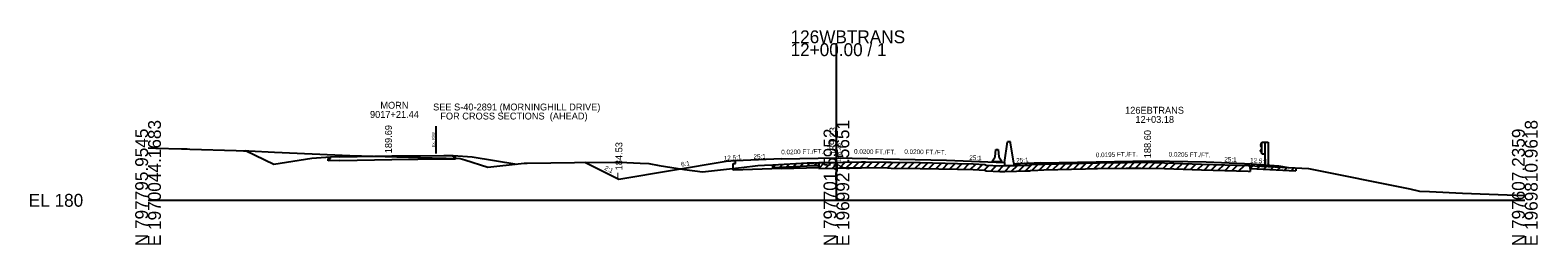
# Model space of a CAD drawing. Extents: x -6494 to 1970605, y -10 to 798140.
# Drawn here: x -25.7 to 302.8, y 4490.3 to 4537 of the extents above; entities that cross this region are included whole.
import ezdxf

# ---------------------------------------------------------------- set-up
doc = ezdxf.new("R2010")
doc.units = 0
for name, color, linetype in [('Default', 7, 'Continuous'), ('RD_GPK_XS_Cell', 7, 'Continuous'), ('RD_XS_Base', 7, 'Continuous'), ('RD_XS_EarthShd', 7, 'Continuous'), ('RD_XS_ExGround', 7, 'Continuous'), ('RD_XS_ExPaveRet', 7, 'Continuous'), ('RD_XS_ExRW', 7, 'Continuous'), ('RD_XS_GR', 7, 'Continuous'), ('RD_XS_MedBWall', 7, 'Continuous'), ('RD_XS_Misc_Line', 7, 'Continuous'), ('RD_XS_Pave', 7, 'Continuous'), ('RD_XS_PaveOvlay', 7, 'Continuous'), ('RD_XS_PaveShd', 7, 'Continuous'), ('RD_XS_TieSlope', 7, 'Continuous'), ('RD_XS_TX_Elev_EX', 7, 'Continuous'), ('RD_XS_TX_Elev_PR', 7, 'Continuous'), ('RD_XS_TX_Misc', 7, 'Continuous'), ('RD_XS_TX_MkPT', 7, 'Continuous'), ('RD_XS_TX_Notes', 7, 'Continuous'), ('RD_XS_TX_Profile', 7, 'Continuous'), ('RD_XS_TX_ShdSlope', 7, 'Continuous'), ('RD_XS_TX_Slope', 7, 'Continuous'), ('RD_XS_TX_Station', 7, 'Continuous')]:
    doc.layers.add(name, color=color, linetype=linetype)

msp = doc.modelspace()

# ---------------------------------------------------------------- linework, layer by layer
at = {"layer": 'Default'}
for p, q in [((184.58, 4509.45), (184.75, 4511.04)), ((184.75, 4511.04), (185.25, 4511.04)), ((185.25, 4511.04), (185.42, 4509.45)), ((184, 4508.62), (184.58, 4509.45)), ((184, 4508.37), (184, 4508.62)), ((186, 4508.37), (184, 4508.37)), ((185.42, 4509.45), (186, 4508.62)), ((186, 4508.62), (186, 4508.37))]:
    msp.add_line(p, q, dxfattribs=at)
at = {"layer": 'RD_GPK_XS_Cell'}
for p, q in [((150, 4500), (150, 4534.19)), ((0, 4500), (150, 4500)), ((150, 4500), (300, 4500))]:
    msp.add_line(p, q, dxfattribs=at)
at = {"layer": 'RD_XS_Base'}
for p, q in [((39.25, 4509.1), (39.76, 4509.11)), ((39.25, 4508.62), (39.25, 4509.1)), ((41.82, 4508.68), (39.25, 4508.62)), ((39.76, 4509.11), (39.76, 4509.41)), ((64.44, 4508.99), (67.01, 4509)), ((66.5, 4509.48), (66.5, 4509.78)), ((67.01, 4509.48), (66.5, 4509.48)), ((67.01, 4509), (67.01, 4509.48)), ((127.5, 4508.01), (128, 4508.03)), ((127.5, 4506.53), (127.5, 4508.01)), ((128, 4508.03), (128, 4508.59)), ((240.56, 4507.53), (240.56, 4507.96)), ((138, 4506.95), (127.5, 4506.53)), ((138, 4506.95), (146.14, 4507.12))]:
    msp.add_line(p, q, dxfattribs=at)
at = {"layer": 'RD_XS_EarthShd'}
for p, q in [((39.76, 4509.41), (35.65, 4509.09)), ((66.5, 4509.78), (70.61, 4509.46)), ((128, 4508.59), (126, 4508.43)), ((240.56, 4507.96), (242.56, 4507.8))]:
    msp.add_line(p, q, dxfattribs=at)
at = {"layer": 'RD_XS_ExGround'}
msp.add_lwpolyline([(0, 4511.4), (1.7, 4511.34), (7.29, 4511.2), (7.85, 4511.19), (8.49, 4511.18), (9.11, 4511.16), (19.21, 4510.87), (20.79, 4510.78), (21.95, 4510.75), (27.54, 4510.5), (43.95, 4509.72), (61.9, 4509.24), (68, 4509.12), (69.05, 4508.84), (74.06, 4507.18), (81.3, 4507.99), (81.95, 4508.07), (82.63, 4508.08), (92.95, 4508.23), (101.72, 4508.28), (102.88, 4508.29), (107.2, 4508.1), (109.14, 4507.99), (111.37, 4507.58), (116.92, 4506.67), (120.84, 4506.22), (129.34, 4507.16), (132.84, 4507.59), (134.33, 4507.66), (136.14, 4507.73), (143.64, 4508.13), (144.36, 4508.17), (145.18, 4508.19), (150, 4508.26), (151.48, 4508.29), (155.43, 4508.35), (156.33, 4508.37), (161.12, 4508.29), (161.44, 4508.29), (161.92, 4508.28), (168.26, 4508.2), (176.38, 4508), (179.8, 4507.92), (182.37, 4507.78), (182.62, 4507.66), (185.59, 4507.53), (186.73, 4507.55), (189.22, 4507.57), (191.06, 4507.63), (192.1, 4507.67), (192.31, 4507.77), (193.89, 4507.83), (195.22, 4507.89), (204.26, 4508.09), (206.12, 4508.14), (206.92, 4508.15), (213.14, 4508.25), (216.4, 4508.28), (221.48, 4508.17), (229.54, 4507.9), (239.69, 4507.57), (252.85, 4506.92), (274.92, 4502.46), (277.03, 4501.99), (279.25, 4501.89), (286.4, 4501.54), (300, 4501.06)], dxfattribs=at)
at = {"layer": 'RD_XS_ExPaveRet'}
for p, q in [((136.14, 4507.11), (136.14, 4507.73)), ((136.14, 4507.11), (143.64, 4507.51)), ((143.64, 4507.51), (144.36, 4507.55)), ((144.36, 4507.55), (145.18, 4507.56)), ((145.18, 4507.56), (146.14, 4507.58)), ((146.14, 4506.95), (146.14, 4508.2)), ((146.14, 4508.2), (146.14, 4507.58)), ((240.13, 4507.55), (240.13, 4506.3)), ((240.13, 4506.92), (240.13, 4507.55)), ((146.14, 4506.95), (150, 4507.01)), ((150, 4507.01), (151.48, 4507.04)), ((151.48, 4507.04), (155.43, 4507.1)), ((155.43, 4507.1), (156.33, 4507.12)), ((156.33, 4507.12), (161.12, 4507.04)), ((161.12, 4507.04), (161.44, 4507.04)), ((161.44, 4507.04), (161.92, 4507.03)), ((161.92, 4507.03), (168.26, 4506.95)), ((168.26, 4506.95), (176.38, 4506.75)), ((176.38, 4506.75), (179.8, 4506.67)), ((179.8, 4506.67), (182.37, 4506.53)), ((182.37, 4506.53), (182.62, 4506.41)), ((182.62, 4506.41), (185.59, 4506.28)), ((185.59, 4506.28), (186.73, 4506.3)), ((186.73, 4506.3), (189.22, 4506.32)), ((189.22, 4506.32), (191.06, 4506.38)), ((191.06, 4506.38), (192.1, 4506.42)), ((192.1, 4506.42), (192.31, 4506.52)), ((192.31, 4506.52), (193.89, 4506.58)), ((193.89, 4506.58), (195.22, 4506.64)), ((195.22, 4506.64), (204.26, 4506.84)), ((204.26, 4506.84), (206.12, 4506.89)), ((206.12, 4506.89), (206.92, 4506.9)), ((206.92, 4506.9), (213.14, 4507)), ((213.14, 4507), (216.4, 4507.03)), ((216.4, 4507.03), (221.48, 4506.92)), ((221.48, 4506.92), (229.54, 4506.65)), ((229.54, 4506.65), (239.69, 4506.32)), ((239.69, 4506.32), (240.13, 4506.3)), ((240.13, 4506.92), (250.13, 4506.43)), ((250.13, 4507.06), (250.13, 4506.43))]:
    msp.add_line(p, q, dxfattribs=at)
at = {"layer": 'RD_XS_ExRW'}
msp.add_line((62.74, 4516.17), (62.74, 4510.17), dxfattribs=at)
at = {"layer": 'RD_XS_GR'}
for p, q in [((242.7, 4512.51), (242.43, 4512.07)), ((242.43, 4512.07), (242.43, 4511.96)), ((242.43, 4511.96), (242.7, 4511.52)), ((242.43, 4510.81), (242.7, 4511.25)), ((242.43, 4510.7), (242.43, 4510.81)), ((242.7, 4512.67), (243.37, 4512.67)), ((242.7, 4510.1), (242.7, 4512.67)), ((243.37, 4512.67), (244.04, 4512.67)), ((243.37, 4512.67), (243.37, 4507.73)), ((244.04, 4512.67), (244.04, 4507.62)), ((242.7, 4510.26), (242.43, 4510.7)), ((242.7, 4510.1), (243.37, 4510.1))]:
    msp.add_line(p, q, dxfattribs=at)
at = {"layer": 'RD_XS_MedBWall'}
for p, q in [((186.62, 4508.25), (187.29, 4512.73)), ((187.96, 4512.73), (187.29, 4512.73)), ((187.96, 4512.53), (187.96, 4512.73)), ((188.62, 4508.05), (187.96, 4512.53)), ((186.62, 4508.25), (186.62, 4507.55)), ((188.62, 4508.05), (188.62, 4507.56))]:
    msp.add_line(p, q, dxfattribs=at)
at = {"layer": 'RD_XS_Misc_Line'}
for p, q in [((136.14, 4507.11), (136.8, 4507.77)), ((137.64, 4507.19), (138.3, 4507.85)), ((139.14, 4507.27), (139.8, 4507.93)), ((140.64, 4507.35), (141.3, 4508.01)), ((142.14, 4507.43), (142.8, 4508.09)), ((143.64, 4507.51), (144.3, 4508.17)), ((145.14, 4507.56), (145.78, 4508.19)), ((146.14, 4506.95), (147.42, 4508.22)), ((147.65, 4506.97), (148.92, 4508.24)), ((149.15, 4507), (150.42, 4508.27)), ((150.65, 4507.02), (151.92, 4508.29)), ((152.15, 4507.05), (153.42, 4508.32)), ((153.65, 4507.07), (154.92, 4508.35)), ((155.15, 4507.1), (156.42, 4508.37)), ((156.65, 4507.12), (157.88, 4508.35)), ((158.15, 4507.09), (159.38, 4508.32)), ((159.65, 4507.07), (160.88, 4508.3)), ((161.15, 4507.04), (162.38, 4508.27)), ((162.65, 4507.02), (163.89, 4508.25)), ((164.15, 4507), (165.39, 4508.23)), ((165.65, 4506.98), (166.89, 4508.21)), ((167.15, 4506.96), (168.39, 4508.19)), ((168.66, 4506.94), (169.88, 4508.16)), ((170.16, 4506.9), (171.38, 4508.12)), ((171.66, 4506.87), (172.88, 4508.09)), ((173.16, 4506.83), (174.38, 4508.05)), ((174.66, 4506.79), (175.88, 4508.01)), ((176.16, 4506.76), (177.38, 4507.98)), ((177.66, 4506.72), (178.88, 4507.94)), ((179.16, 4506.69), (180.37, 4507.89)), ((180.66, 4506.63), (181.85, 4507.81)), ((182.16, 4506.55), (183.25, 4507.63)), ((183.66, 4506.36), (184.86, 4507.56)), ((185.16, 4506.3), (186.41, 4507.55)), ((186.66, 4506.3), (187.92, 4507.56)), ((188.16, 4506.31), (189.43, 4507.57)), ((189.66, 4506.33), (190.96, 4507.63)), ((191.17, 4506.39), (192.56, 4507.78)), ((192.67, 4506.54), (193.96, 4507.83)), ((194.17, 4506.59), (195.47, 4507.89)), ((195.67, 4506.65), (196.95, 4507.93)), ((197.17, 4506.68), (198.45, 4507.96)), ((198.67, 4506.72), (199.95, 4508)), ((200.17, 4506.75), (201.45, 4508.03)), ((201.67, 4506.79), (202.95, 4508.06)), ((203.17, 4506.82), (204.45, 4508.1)), ((204.67, 4506.85), (205.95, 4508.13)), ((206.17, 4506.89), (207.44, 4508.16)), ((207.67, 4506.91), (208.94, 4508.18)), ((209.17, 4506.93), (210.44, 4508.2)), ((210.67, 4506.96), (211.94, 4508.23)), ((212.18, 4506.98), (213.44, 4508.25)), ((213.68, 4507), (214.94, 4508.27)), ((215.18, 4507.02), (216.44, 4508.28)), ((216.68, 4507.03), (217.9, 4508.25)), ((218.18, 4506.99), (219.4, 4508.22)), ((219.68, 4506.96), (220.9, 4508.18)), ((221.18, 4506.93), (222.39, 4508.14)), ((222.68, 4506.88), (223.89, 4508.09)), ((224.18, 4506.83), (225.39, 4508.04)), ((225.68, 4506.78), (226.89, 4507.99)), ((227.18, 4506.73), (228.39, 4507.94)), ((228.68, 4506.68), (229.89, 4507.89)), ((230.18, 4506.63), (231.39, 4507.84)), ((231.68, 4506.58), (232.89, 4507.79)), ((233.18, 4506.53), (234.4, 4507.74)), ((234.69, 4506.48), (235.9, 4507.69)), ((236.19, 4506.43), (237.4, 4507.64)), ((237.69, 4506.38), (238.9, 4507.59)), ((240.13, 4506.92), (240.73, 4507.52)), ((241.63, 4506.85), (242.23, 4507.44)), ((243.13, 4506.77), (243.73, 4507.37)), ((244.63, 4506.7), (245.23, 4507.3)), ((246.13, 4506.63), (246.73, 4507.22)), ((247.63, 4506.55), (248.23, 4507.15)), ((249.14, 4506.48), (249.73, 4507.08))]:
    msp.add_line(p, q, dxfattribs=at)
at = {"layer": 'RD_XS_Pave'}
for p, q in [((41.82, 4509.46), (53.13, 4509.69)), ((41.82, 4508.68), (53.13, 4508.91)), ((53.13, 4509.69), (64.44, 4509.77)), ((53.13, 4508.91), (64.44, 4508.99)), ((138, 4508.99), (150, 4509.23)), ((150, 4509.23), (174, 4508.75)), ((194.54, 4508.14), (218.55, 4508.6)), ((218.55, 4508.6), (230.55, 4508.36))]:
    msp.add_line(p, q, dxfattribs=at)
at = {"layer": 'RD_XS_PaveOvlay'}
for p, q in [((146.14, 4508.2), (150, 4508.26)), ((146.14, 4508.2), (146.14, 4507.12)), ((150, 4508.26), (151.48, 4508.29)), ((151.48, 4508.29), (155.43, 4508.35)), ((155.43, 4508.35), (156.33, 4508.37)), ((156.33, 4508.37), (161.12, 4508.29)), ((161.12, 4508.29), (161.44, 4508.29)), ((161.44, 4508.29), (161.92, 4508.28)), ((161.92, 4508.28), (168.26, 4508.2)), ((168.26, 4508.2), (176.38, 4508)), ((176.38, 4508), (179.8, 4507.92)), ((179.8, 4507.92), (182.37, 4507.78)), ((182.37, 4507.78), (182.62, 4507.66)), ((182.62, 4507.66), (185.59, 4507.53)), ((185.59, 4507.53), (186.62, 4507.55)), ((221.48, 4508.17), (229.54, 4507.9)), ((229.54, 4507.9), (239.69, 4507.57)), ((239.69, 4507.57), (240.13, 4507.55)), ((240.13, 4507.55), (240.56, 4507.53))]:
    msp.add_line(p, q, dxfattribs=at)
at = {"layer": 'RD_XS_PaveShd'}
for p, q in [((41.82, 4509.46), (39.76, 4509.41)), ((64.44, 4509.77), (66.5, 4509.78)), ((138, 4508.99), (128, 4508.59)), ((174, 4508.75), (186.62, 4508.25)), ((186.62, 4508.25), (186.62, 4507.55)), ((194.54, 4508.14), (188.62, 4507.9)), ((230.55, 4508.36), (240.56, 4507.96))]:
    msp.add_line(p, q, dxfattribs=at)
at = {"layer": 'RD_XS_TieSlope'}
for p, q in [((27.42, 4507.76), (21.23, 4510.77)), ((35.65, 4509.09), (27.42, 4507.76)), ((70.61, 4509.46), (80.34, 4507.88)), ((102.6, 4504.53), (95.18, 4508.24)), ((126, 4508.43), (102.6, 4504.53)), ((242.56, 4507.8), (246.31, 4507.5)), ((246.31, 4507.5), (248.46, 4507.14))]:
    msp.add_line(p, q, dxfattribs=at)

# ---------------------------------------------------------------- texts
at = {"layer": 'RD_GPK_XS_Cell'}
for s, p in [('126WBTRANS', (140, 4534.19)), ('12+00.00 / 1', (140, 4531.39)), ('EL 180', (-26, 4498.6))]:
    msp.add_text(s, height=2.8, dxfattribs=at).set_placement(p)
for s, p in [('N 797795.9545', (0, 4490)), ('E 1970044.1683', (2.8, 4490)), ('N 797701.5952', (150, 4490)), ('E 1969927.5651', (152.8, 4490)), ('N 797607.2359', (300, 4490)), ('E 1969810.9618', (302.8, 4490))]:
    msp.add_text(s, height=2.8, rotation=90, dxfattribs=at).set_placement(p)
at = {"layer": 'RD_XS_ExRW'}
msp.add_text('Ex. R/W ', height=0.65, rotation=90, dxfattribs=at).set_placement((62.49, 4511.55))
at = {"layer": 'RD_XS_TX_Elev_EX'}
msp.add_text('188.26', height=1, rotation=90, dxfattribs=at).set_placement((151, 4508.26))
at = {"layer": 'RD_XS_TX_Elev_PR'}
for s, p in [(' 189.69', (53.13, 4509.69)), (' 189.23', (150, 4509.23)), (' 188.60', (218.55, 4508.6))]:
    msp.add_text(s, height=1.5, rotation=90, dxfattribs=at).set_placement(p)
at = {"layer": 'RD_XS_TX_Misc'}
msp.add_text('184.53', height=1.5, rotation=90, dxfattribs=at).set_placement((103.35, 4506.53))
at = {"layer": 'RD_XS_TX_MkPT'}
msp.add_text('L', height=1.5, dxfattribs=at).set_placement((102.09, 4504.53))
at = {"layer": 'RD_XS_TX_Notes'}
for s, p in [('SEE S-40-2891 (MORNINGHILL DRIVE)', (62.11, 4519.56)), ('FOR CROSS SECTIONS  (AHEAD)', (63.68, 4517.59))]:
    msp.add_text(s, height=1.5, dxfattribs=at).set_placement(p)
at = {"layer": 'RD_XS_TX_Profile'}
for rotation, p in [(2.2906, (131.94, 4509)), (357.7094, (178.93, 4508.81)), (2.2899, (189.19, 4508.17)), (357.7101, (234.51, 4508.45))]:
    msp.add_text('25:1', height=1, rotation=rotation, dxfattribs=at).set_placement(p)
at = {"layer": 'RD_XS_TX_ShdSlope'}
for rotation, p in [(4.5739, (125.5, 4508.65)), (355.4274, (240.1, 4508.25))]:
    msp.add_text('12.5:1', height=1, rotation=rotation, dxfattribs=at).set_placement(p)
at = {"layer": 'RD_XS_TX_Slope'}
for s, rotation, p in [('0.0200 FT./FT.', 1.1458, (137.98, 4509.99)), ('0.0200 FT./FT.', 358.8542, (153.83, 4510.16)), ('0.0200 FT./FT.', 358.8542, (164.78, 4510.12)), ('2:1', 333.4349, (99.34, 4506.72)), ('6:1', 9.4623, (116.22, 4507.31)), ('0.0195 FT./FT.', 1.1165, (206.53, 4509.37)), ('0.0205 FT./FT.', 358.8264, (222.38, 4509.53))]:
    msp.add_text(s, height=1, rotation=rotation, dxfattribs=at).set_placement(p)
at = {"layer": 'RD_XS_TX_Station'}
for s, p in [('MORN', (50.62, 4519.94)), ('9017+21.44', (48.36, 4517.94)), ('126EBTRANS', (212.9, 4518.85)), ('12+03.18', (215.15, 4516.85))]:
    msp.add_text(s, height=1.5, dxfattribs=at).set_placement(p)

doc.saveas('drawing.dxf')
